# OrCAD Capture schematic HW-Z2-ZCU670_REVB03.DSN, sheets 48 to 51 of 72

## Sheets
48 048 PMIC 2 Power Stage: size Custom
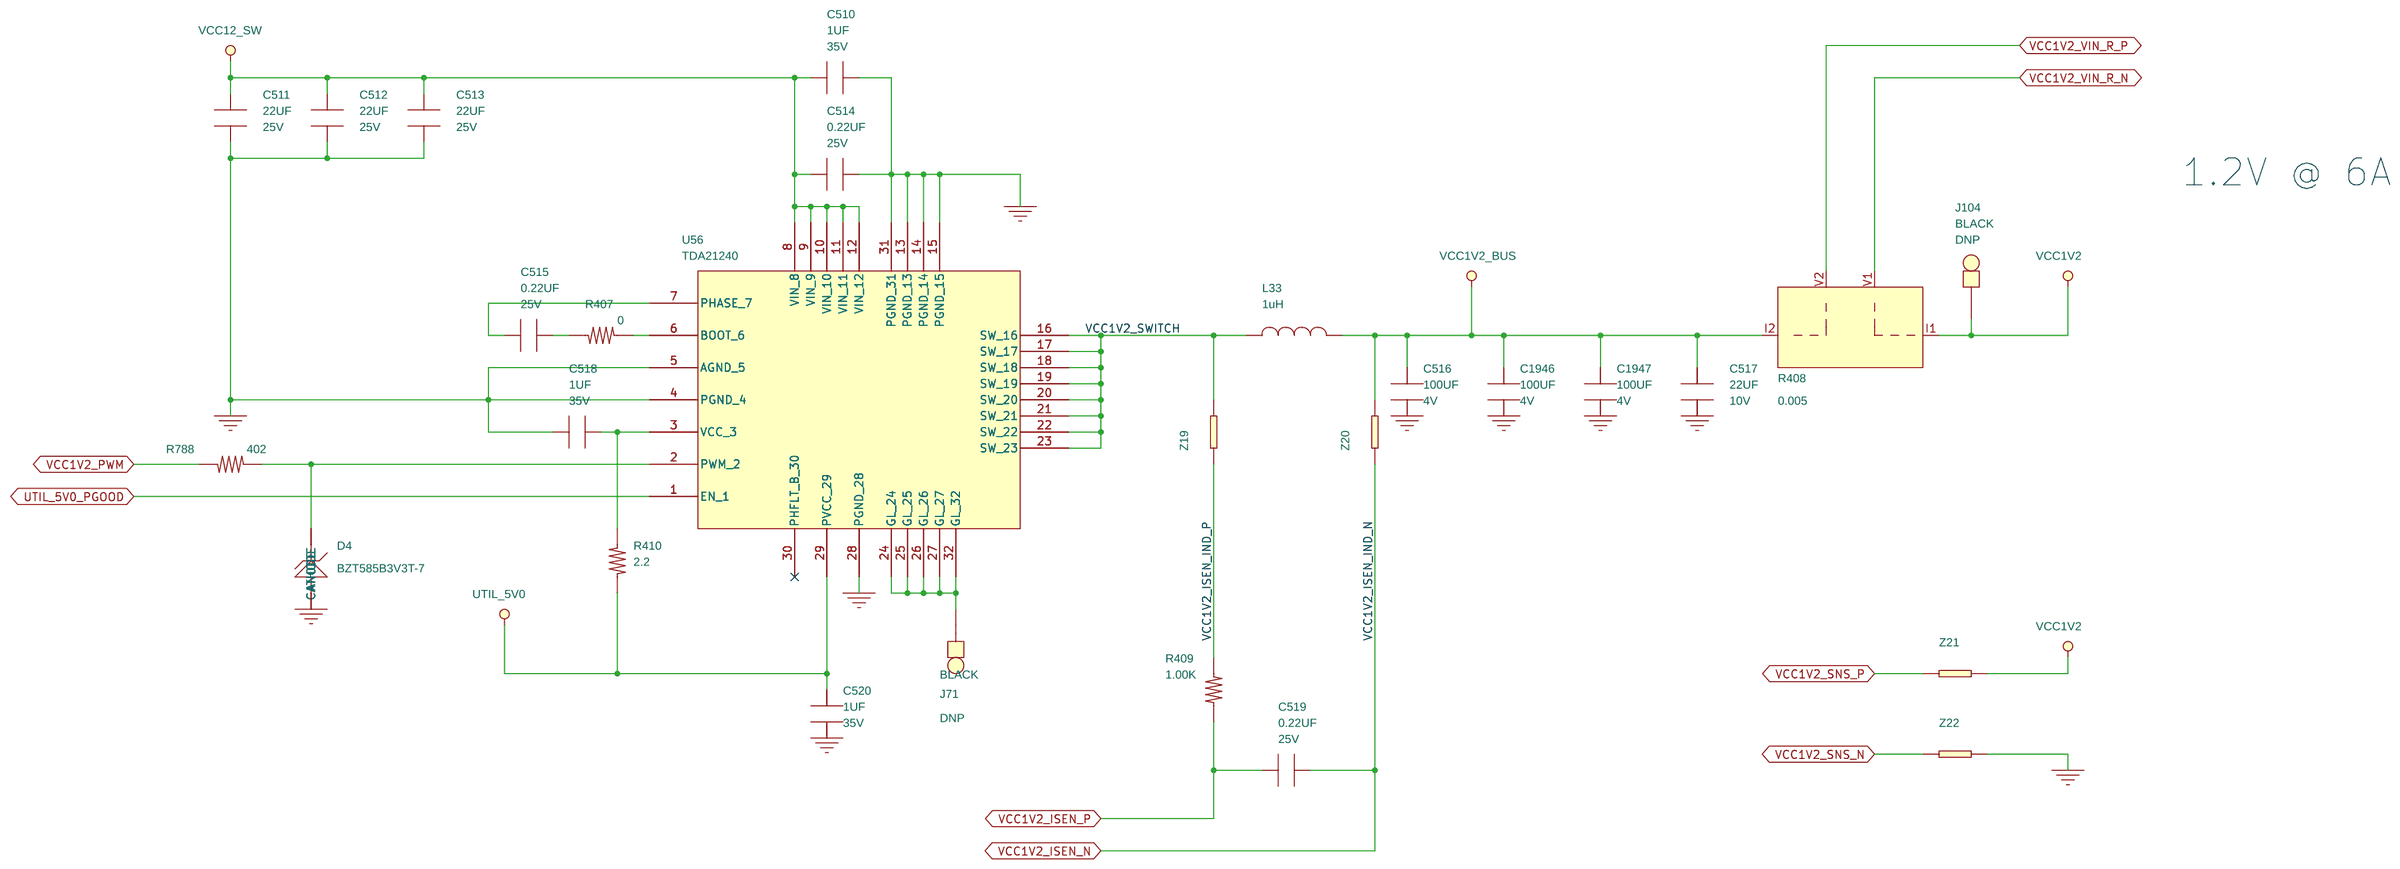
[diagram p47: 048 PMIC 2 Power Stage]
49 049 PMIC 3: size Custom
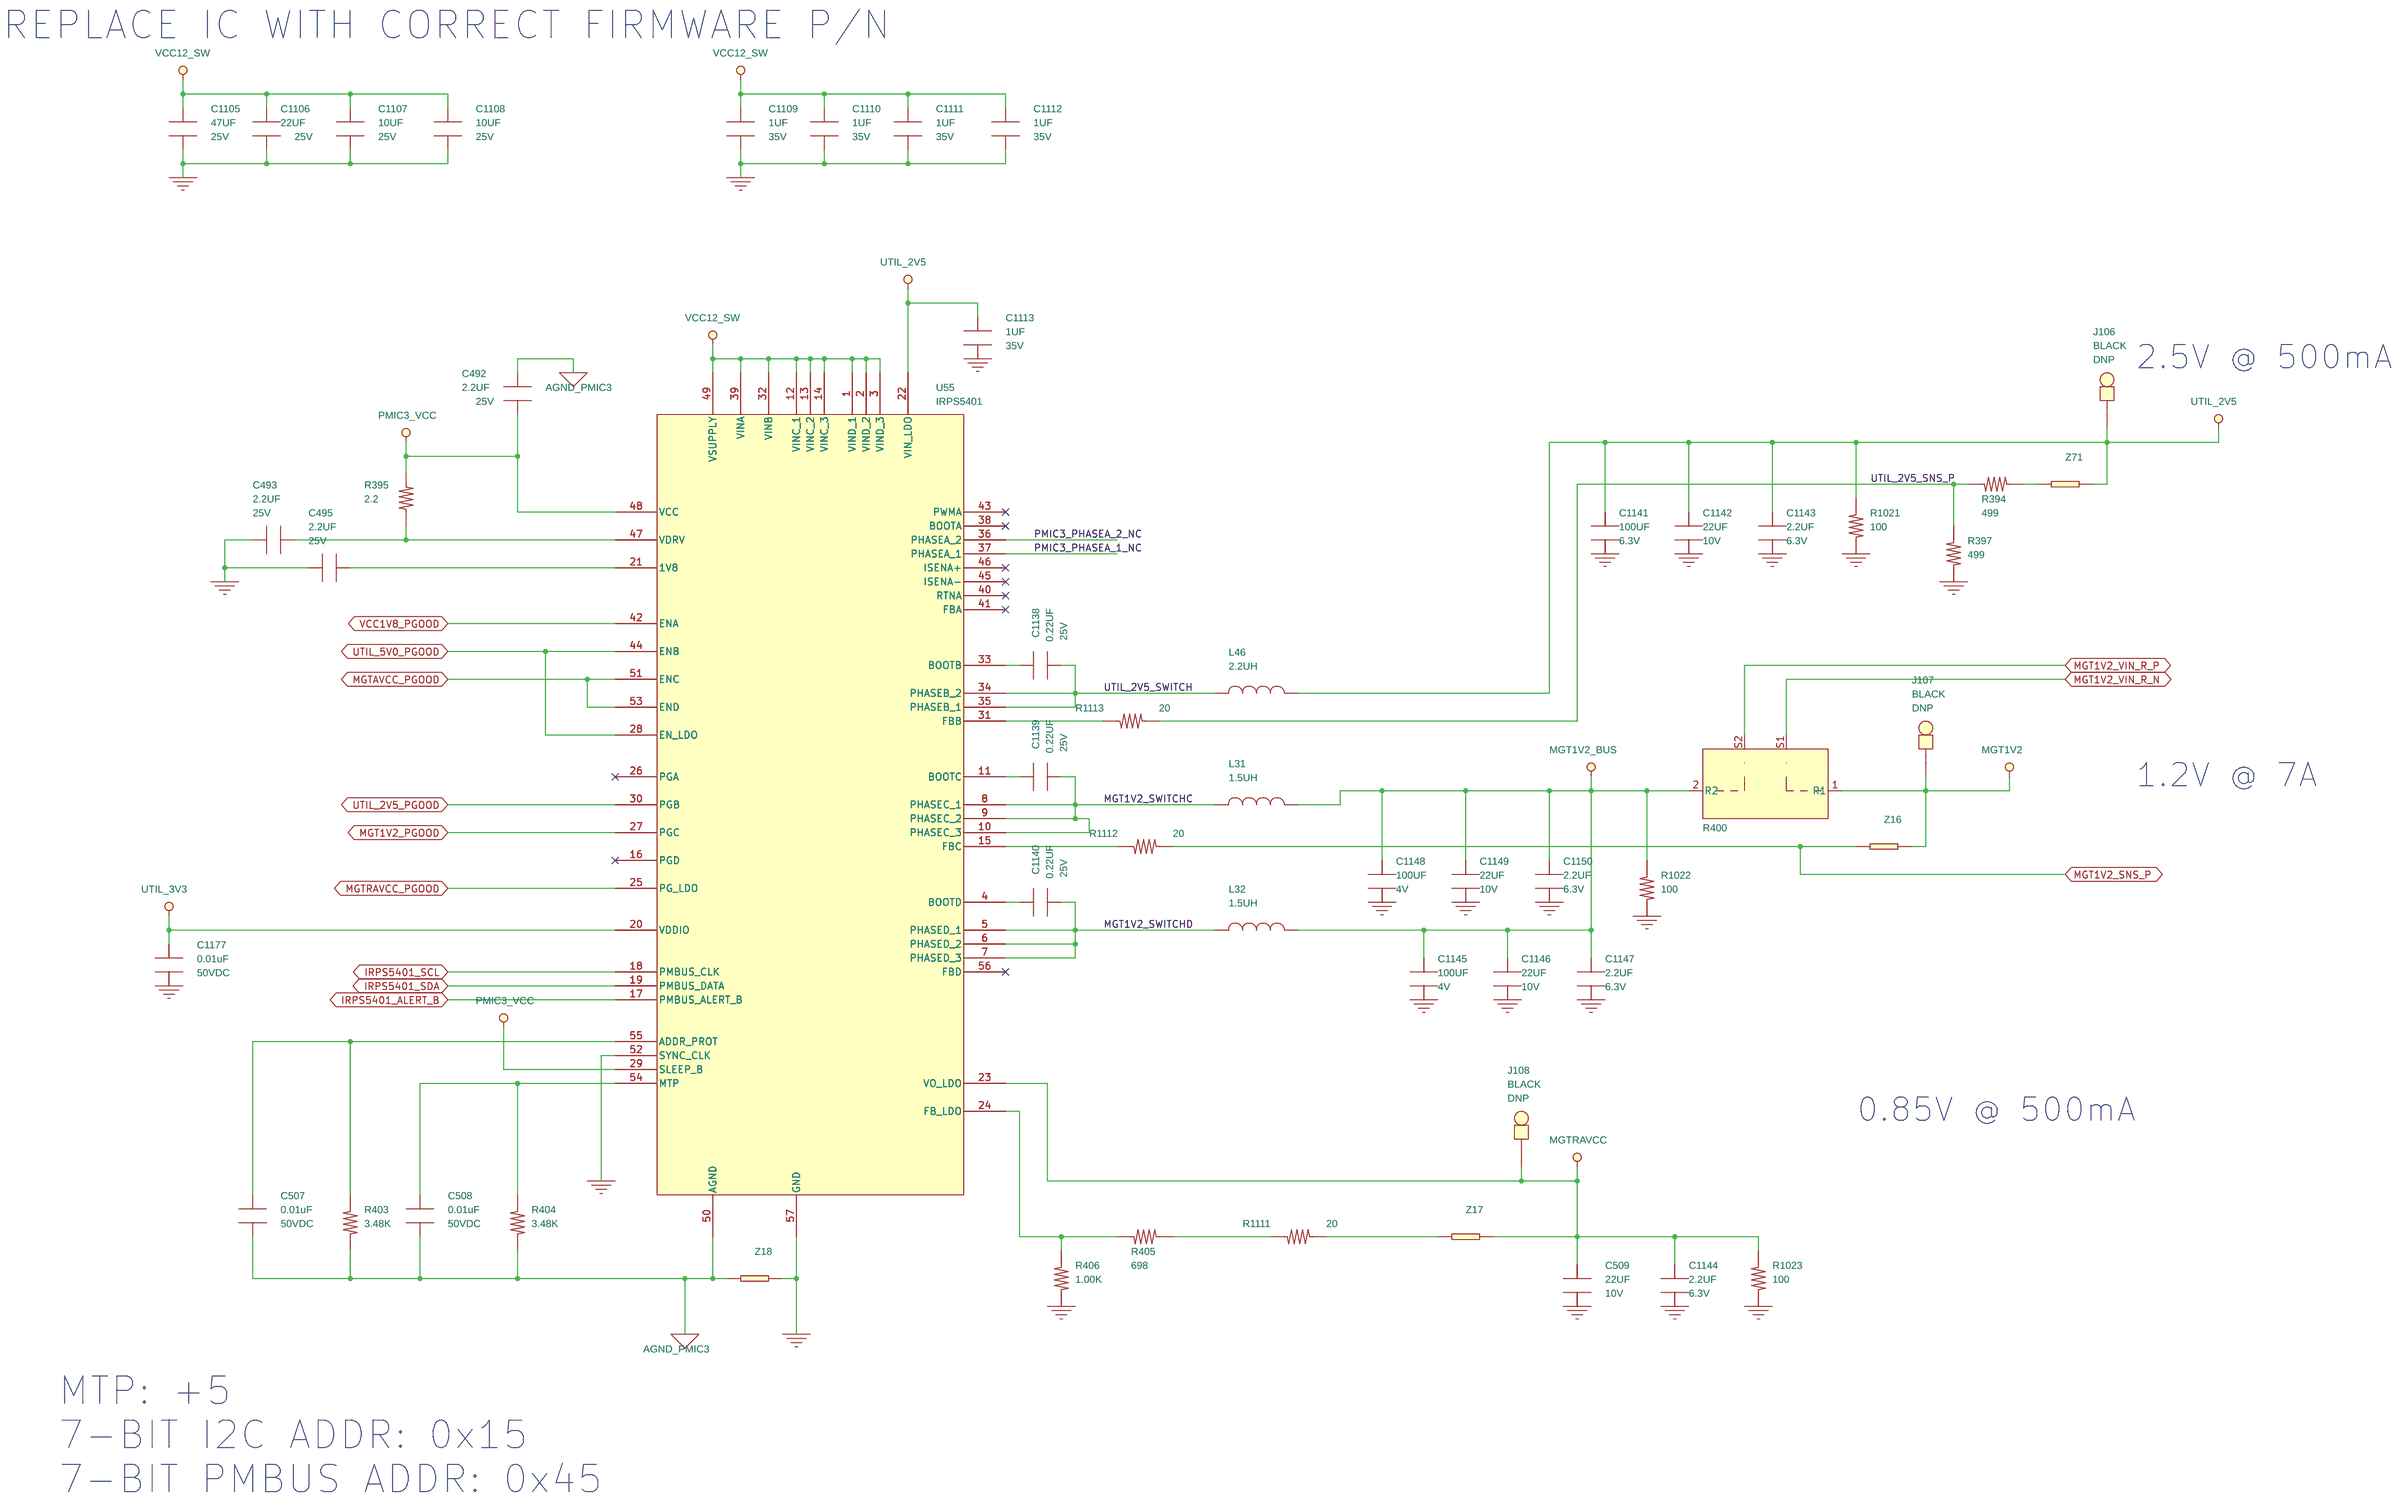
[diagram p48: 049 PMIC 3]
50 050 VCCINT_IO_BRAM_PS 18A Reg: size Custom
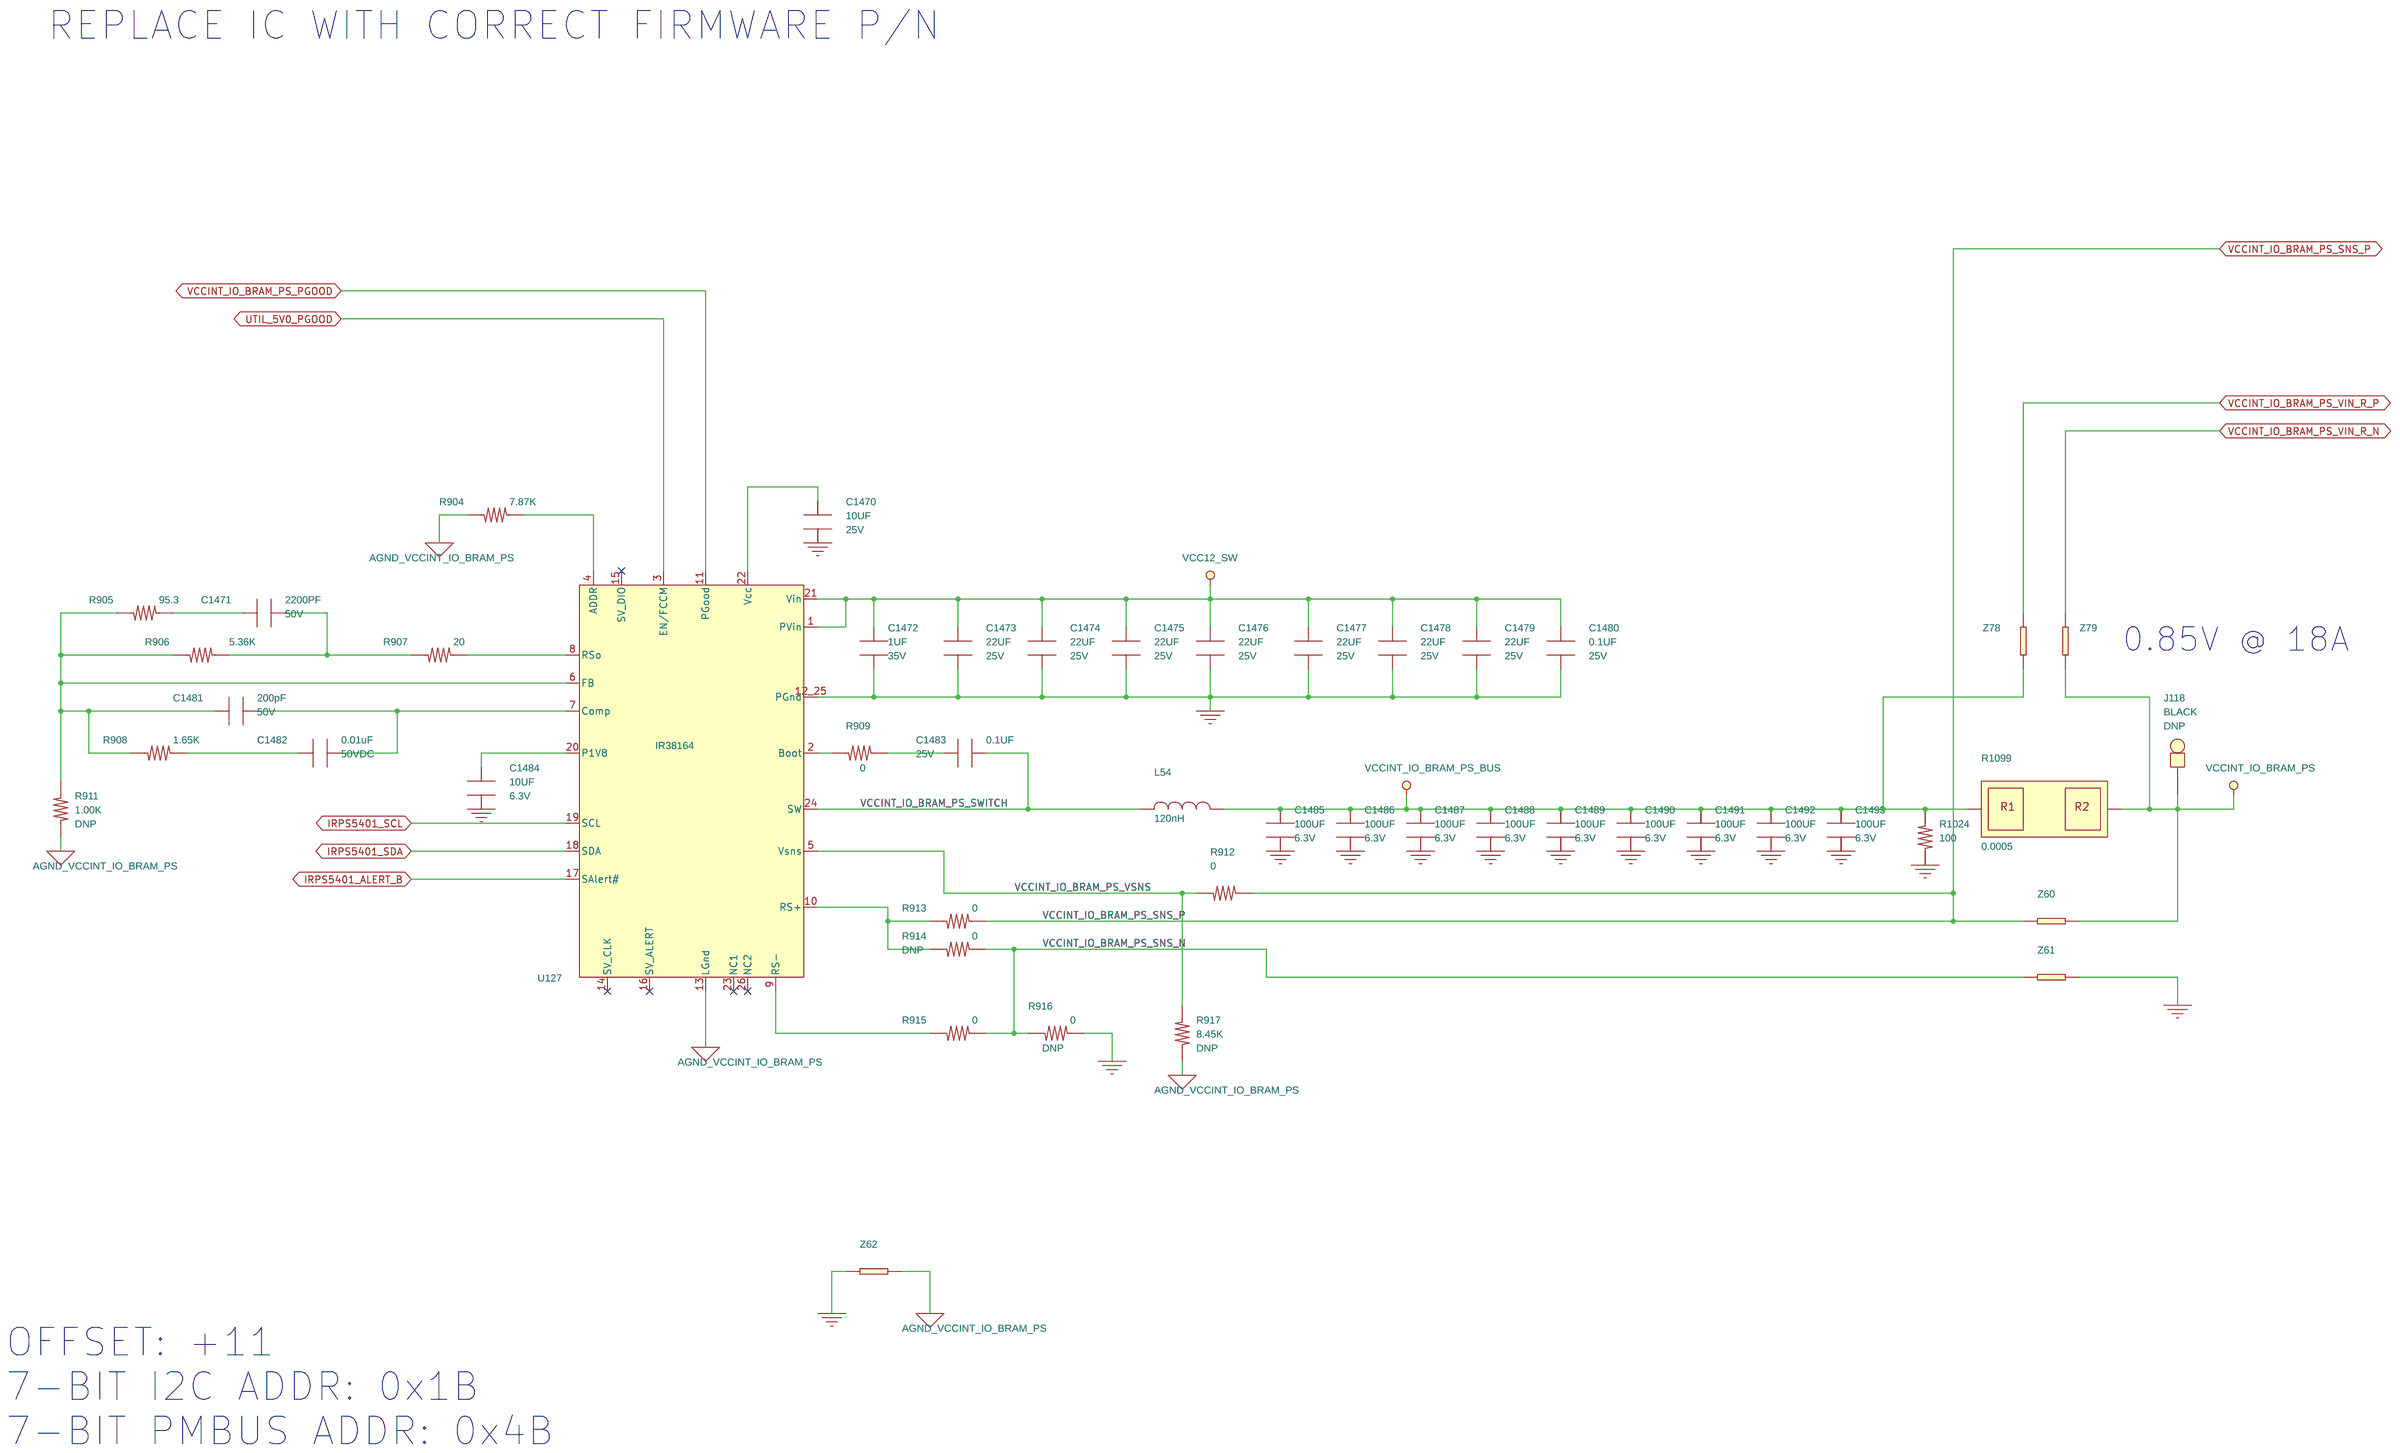
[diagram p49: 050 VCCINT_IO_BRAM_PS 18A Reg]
51 051 MGTAVCC 4A Regulator: size Custom
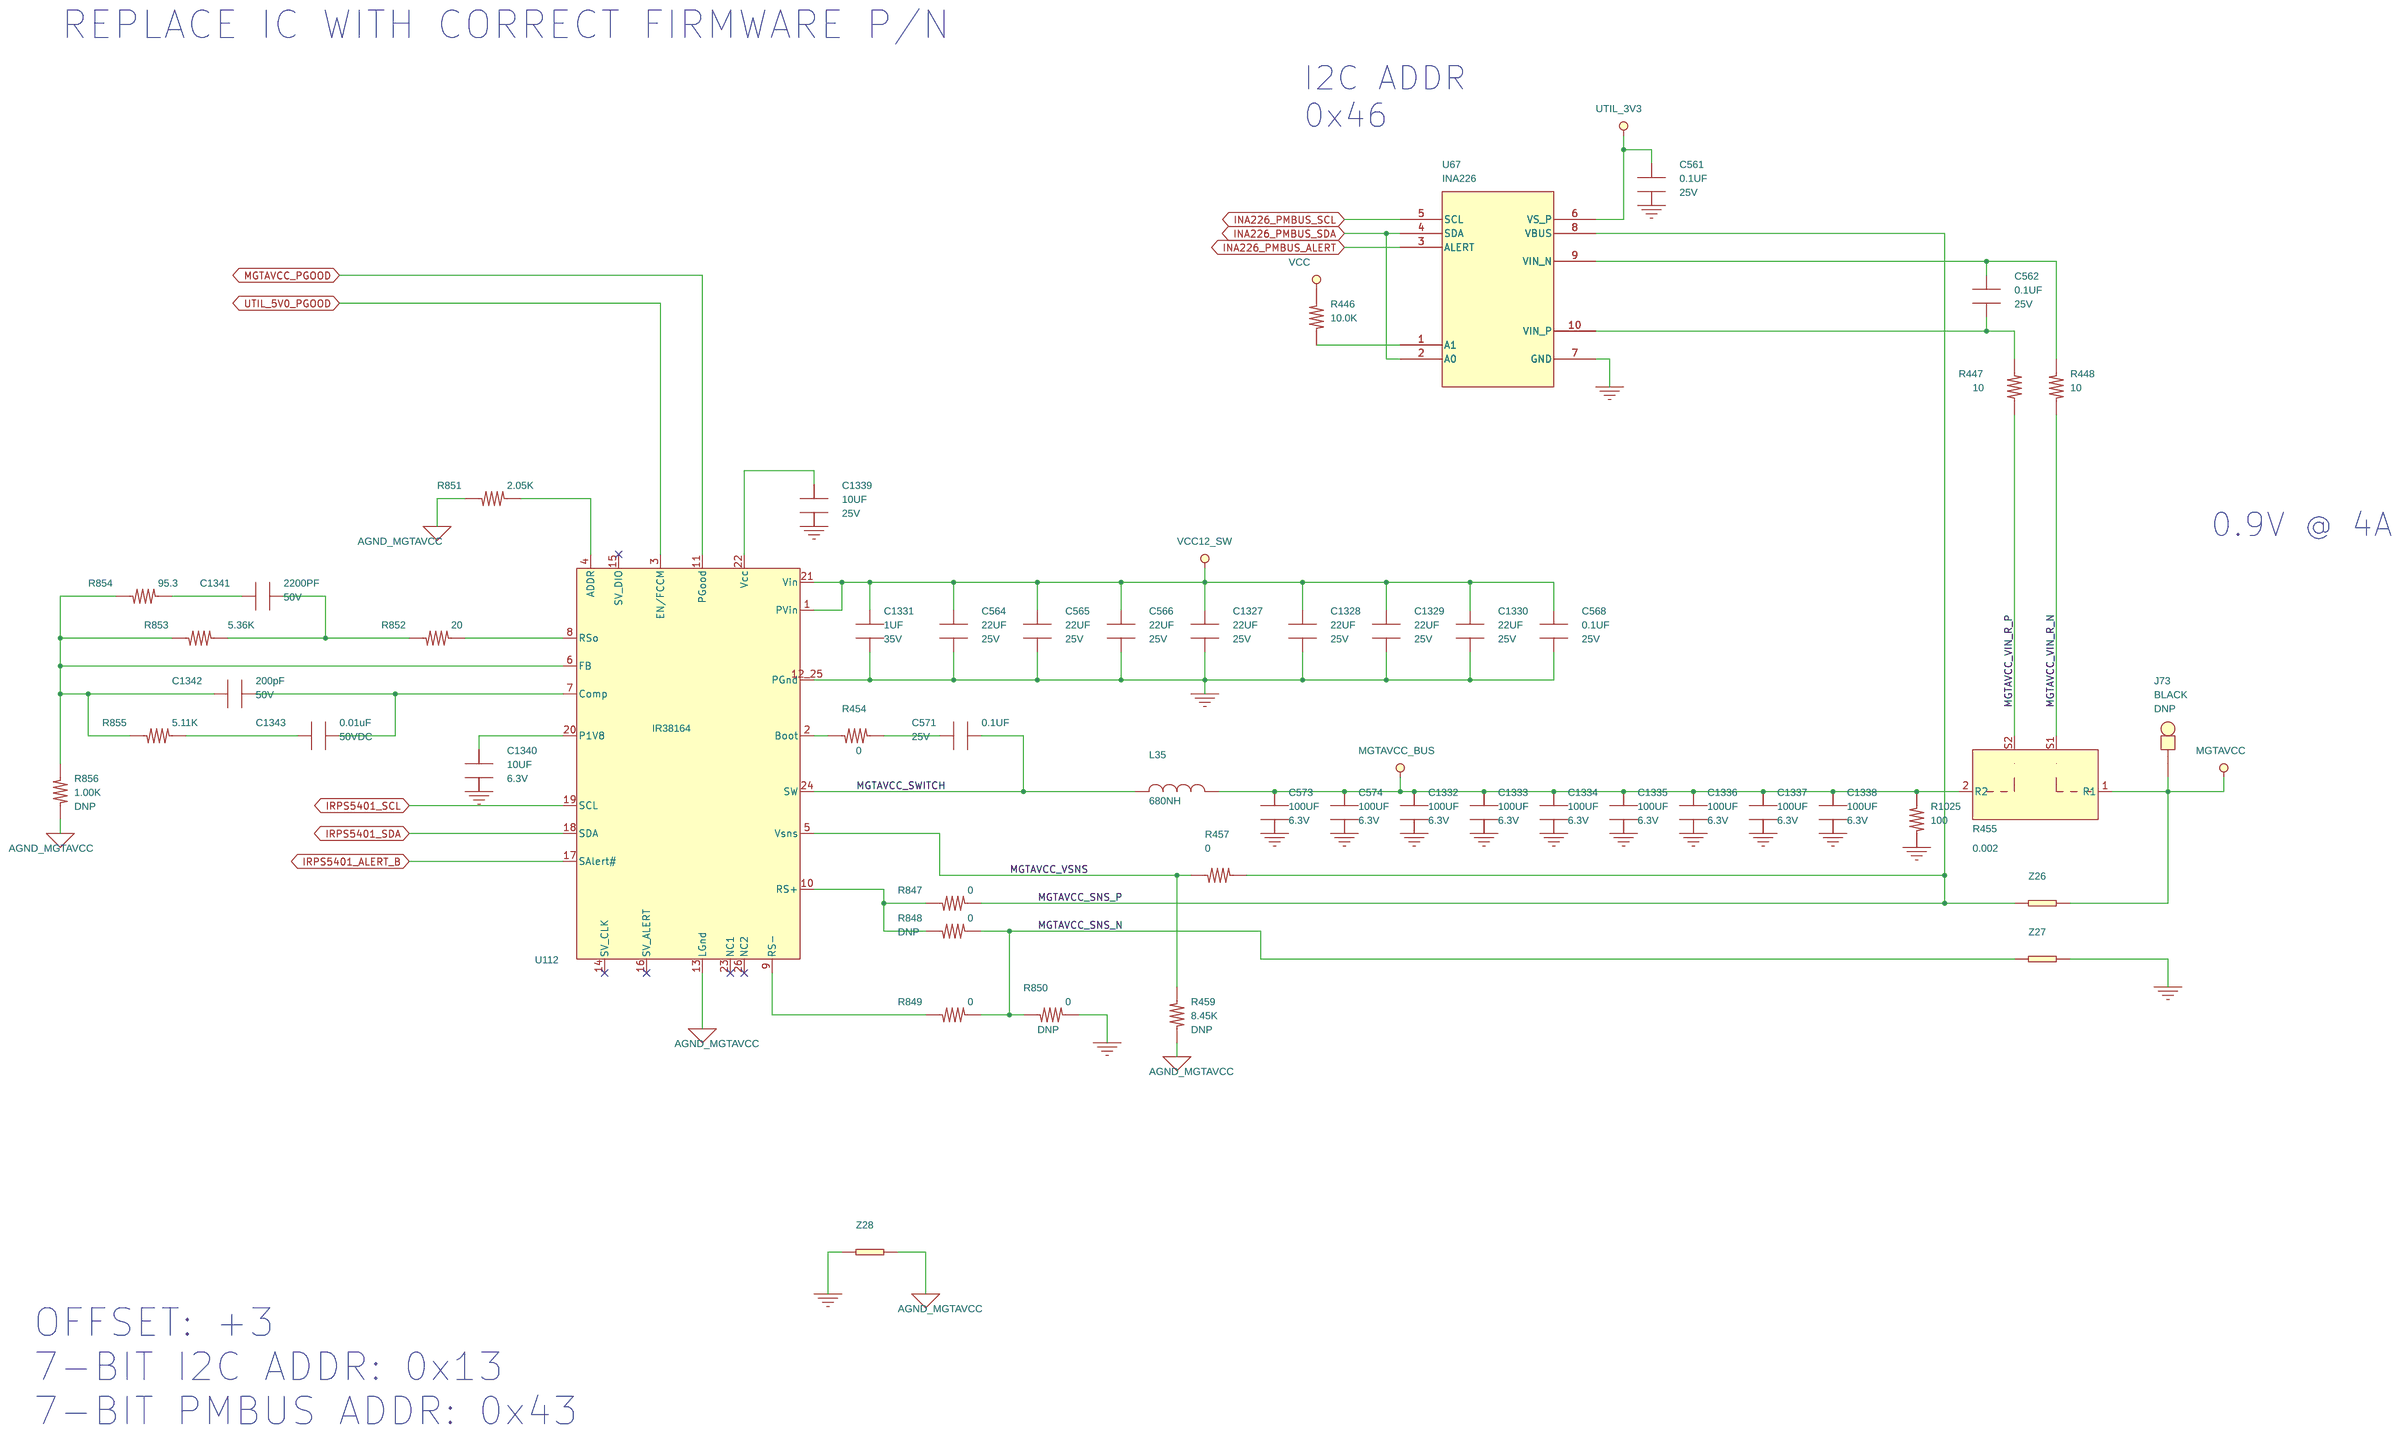
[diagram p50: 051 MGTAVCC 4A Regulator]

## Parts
sheet 048 PMIC 2 Power Stage
C510  1UF  [CAPC100X50X60]
C511  22UF  [CAPC320X160X180]
C512  22UF  [CAPC320X160X180]
C513  22UF  [CAPC320X160X180]
C514  0.22UF  [CAPC100X50X55]
C515  0.22UF  [CAPC100X50X55]
C516  100UF  [CAPC200X125X145]
C517  22UF  [CAPC200X125X145]
C518  1UF  [CAPC100X50X60]
C519  0.22UF  [CAPC100X50X55]
C520  1UF  [CAPC100X50X60]
C1946  100UF  [CAPC200X125X145]
C1947  100UF  [CAPC200X125X145]
D4  BZT585B3V3T-7  [SOD_523]
J71  BLACK  [TP_KEY_MINI]
J104  BLACK  [TP_KEY_MINI]
L33  1uH  [IND_WURTH_74439344010]
R407  0  [RESC100X50X40]
R408  0.005  [1224_SMT]
R409  1.00K  [RESC100X50X40]
R410  2.2  [RESC160X80X55]
R788  402  [RESC100X50X40]
U56  TDA21240  [TDA21240]
Z19  0201_SHORT  [0201_SHORT]
Z20  0201_SHORT  [0201_SHORT]
Z21  0201_SHORT  [0201_SHORT]
Z22  0201_SHORT  [0201_SHORT]
sheet 049 PMIC 3
C492  2.2UF  [CAPC200X125X135]
C493  2.2UF  [CAPC200X125X135]
C495  2.2UF  [CAPC200X125X135]
C507  0.01uF  [CAPC100X50X55]
C508  0.01uF  [CAPC100X50X55]
C509  22UF  [CAPC200X125X145]
C1105  47UF  [CAPC320X160X180]
C1106  22UF  [CAPC320X160X180]
C1107  10UF  [CAPC320X250X220]
C1108  10UF  [CAPC320X250X220]
C1109  1UF  [CAPC100X50X60]
C1110  1UF  [CAPC100X50X60]
C1111  1UF  [CAPC100X50X60]
C1112  1UF  [CAPC100X50X60]
C1113  1UF  [CAPC100X50X60]
C1138  0.22UF  [CAPC100X50X55]
C1139  0.22UF  [CAPC100X50X55]
C1140  0.22UF  [CAPC100X50X55]
C1141  100UF  [CAPC320X160X180]
C1142  22UF  [CAPC200X125X145]
C1143  2.2UF  [CAPC100X50X55]
C1144  2.2UF  [CAPC100X50X55]
C1145  100UF  [CAPC200X125X145]
C1146  22UF  [CAPC200X125X145]
C1147  2.2UF  [CAPC100X50X55]
C1148  100UF  [CAPC200X125X145]
C1149  22UF  [CAPC200X125X145]
C1150  2.2UF  [CAPC100X50X55]
C1177  0.01uF  [CAPC100X50X55]
J106  BLACK  [TP_KEY_MINI]
J107  BLACK  [TP_KEY_MINI]
J108  BLACK  [TP_KEY_MINI]
L31  1.5UH  [IND_SRP4020TA]
L32  1.5UH  [IND_SRP4020TA]
L46  2.2UH  [IND_SRP4020TA]
R394  499  [RESC100X50X40]
R395  2.2  [RESC160X80X55]
R397  499  [RESC100X50X40]
R400  0.002  [RES_WSL3637]
R403  3.48K  [RESC100X50X40]
R404  3.48K  [RESC100X50X40]
R405  698  [RESC100X50X40]
R406  1.00K  [RESC100X50X40]
R1021  100  [RESC100X50X40]
R1022  100  [RESC100X50X40]
R1023  100  [RESC100X50X40]
R1111  20  [RESC100X50X40]
R1112  20  [RESC100X50X40]
R1113  20  [RESC100X50X40]
U55  IRPS5401  [irps5401mtrpbf]
Z16  0201_SHORT  [0201_SHORT]
Z17  0201_SHORT  [0201_SHORT]
Z18  0201_SHORT  [0201_SHORT]
Z71  0201_SHORT  [0201_SHORT]
sheet 050 VCCINT_IO_BRAM_PS 18A Reg
C1470  10UF  [CAPC320X250X220]
C1471  2200PF  [CAPC100X50X55]
C1472  1UF  [CAPC100X50X60]
C1473  22UF  [CAPC320X160X180]
C1474  22UF  [CAPC320X160X180]
C1475  22UF  [CAPC320X160X180]
C1476  22UF  [CAPC320X160X180]
C1477  22UF  [CAPC320X160X180]
C1478  22UF  [CAPC320X160X180]
C1479  22UF  [CAPC320X160X180]
C1480  0.1UF  [CAPC100X50X55]
C1481  200pF  [CAPC100X50X55]
C1482  0.01uF  [CAPC100X50X55]
C1483  0.1UF  [CAPC100X50X55]
C1484  10UF  [CAPC100X50X70]
C1485  100UF  [CAPC320X160X180]
C1486  100UF  [CAPC320X160X180]
C1487  100UF  [CAPC320X160X180]
C1488  100UF  [CAPC320X160X180]
C1489  100UF  [CAPC320X160X180]
C1490  100UF  [CAPC320X160X180]
C1491  100UF  [CAPC320X160X180]
C1492  100UF  [CAPC320X160X180]
C1493  100UF  [CAPC320X160X180]
J118  BLACK  [TP_KEY_MINI]
L54  120nH  [IND_KEMET_MPCH0730]
R904  7.87K  [RESC100X50X40]
R905  95.3  [RESC100X50X40]
R906  5.36K  [RESC100X50X40]
R907  20  [RESC100X50X40]
R908  1.65K  [RESC100X50X40]
R909  0  [RESC100X50X40]
R911  1.00K  [RESC100X50X40]
R912  0  [RESC100X50X40]
R913  0  [RESC100X50X40]
R914  0  [RESC100X50X40]
R915  0  [RESC100X50X40]
R916  0  [RESC100X50X40]
R917  8.45K  [RESC100X50X40]
R1024  100  [RESC100X50X40]
R1099  0.0005  [RES_CSS2775]
U127  IR38164  [QFN_IR38164_26]
Z60  0201_SHORT  [0201_SHORT]
Z61  0201_SHORT  [0201_SHORT]
Z62  0201_SHORT  [0201_SHORT]
Z78  0201_SHORT  [0201_SHORT]
Z79  0201_SHORT  [0201_SHORT]
sheet 051 MGTAVCC 4A Regulator
C561  0.1UF  [CAPC100X50X55]
C562  0.1UF  [CAPC100X50X55]
C564  22UF  [CAPC320X160X180]
C565  22UF  [CAPC320X160X180]
C566  22UF  [CAPC320X160X180]
C568  0.1UF  [CAPC100X50X55]
C571  0.1UF  [CAPC100X50X55]
C573  100UF  [CAPC320X160X180]
C574  100UF  [CAPC320X160X180]
C1327  22UF  [CAPC320X160X180]
C1328  22UF  [CAPC320X160X180]
C1329  22UF  [CAPC320X160X180]
C1330  22UF  [CAPC320X160X180]
C1331  1UF  [CAPC100X50X60]
C1332  100UF  [CAPC320X160X180]
C1333  100UF  [CAPC320X160X180]
C1334  100UF  [CAPC320X160X180]
C1335  100UF  [CAPC320X160X180]
C1336  100UF  [CAPC320X160X180]
C1337  100UF  [CAPC320X160X180]
C1338  100UF  [CAPC320X160X180]
C1339  10UF  [CAPC320X250X220]
C1340  10UF  [CAPC100X50X70]
C1341  2200PF  [CAPC100X50X55]
C1342  200pF  [CAPC100X50X55]
C1343  0.01uF  [CAPC100X50X55]
J73  BLACK  [TP_KEY_MINI]
L35  680NH  [IND_SRP7050TA]
R446  10.0K  [RESC100X50X40]
R447  10  [RESC100X50X40]
R448  10  [RESC100X50X40]
R454  0  [RESC100X50X40]
R455  0.002  [RES_WSL3637]
R457  0  [RESC100X50X40]
R459  8.45K  [RESC100X50X40]
R847  0  [RESC100X50X40]
R848  0  [RESC100X50X40]
R849  0  [RESC100X50X40]
R850  0  [RESC100X50X40]
R851  2.05K  [RESC100X50X40]
R852  20  [RESC100X50X40]
R853  5.36K  [RESC100X50X40]
R854  95.3  [RESC100X50X40]
R855  5.11K  [RESC100X50X40]
R856  1.00K  [RESC100X50X40]
R1025  100  [RESC100X50X40]
U67  INA226  [DGS_MSOP_10]
U112  IR38164  [QFN_IR38164_26]
Z26  0201_SHORT  [0201_SHORT]
Z27  0201_SHORT  [0201_SHORT]
Z28  0201_SHORT  [0201_SHORT]

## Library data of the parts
C510 C518 C520 C1109-C1113 C1331 C1472 = CAP_NP: Cap Cer 1uF 10% 35V X5R 0402; ALT_SYMBOLS: CAPC100X50X60RND; Agile Part Number: CAP-00165-01; CIP Link: http://xsjbrdwin1/CIP-E/Component/Index/All?pn=100192; Dielectric Type: X5R; OWNER: 3709; PRICE: 0.04; Part Type: CERAMIC; PartType: CERAMIC; ROHS: Yes; Tolerance: 10%; Voltage: 35V; barcode: 100192
C511-C513 C564-C566 C1106 C1327-C1330 C1473-C1479 = CAP_NP: Cap Cer 22uF 10% 25V X5R 1206; ALT_SYMBOLS: CAPC320X160X180RND; Agile Part Number: CAP-00058-01; CIP Link: http://xsjbrdwin1/CIP-E/Component/Index/All?pn=100026; Dielectric Type: X5R; OWNER: 3709; PRICE: 0.17; Part Type: CERAMIC; PartType: CERAMIC; ROHS: Yes; Tolerance: 10%; Voltage: 25V; barcode: 100026
C514 C515 C519 C1138-C1140 = CAP_NP: Cap Cer 220nF 10%  25V X6S 0402; ALT_SYMBOLS: (0402,C402-25,CAPC100X50X55L25NRND,CAPC100X50X55L30NRND,CAPC100X50X55L30N); Agile Part Number: CAP-00005-01; CIP Link: http://xsjbrdwin1/CIP-E/Component/Index/All?pn=100180; Dielectric Type: X6S; OWNER: 6176; PRICE: 0.03; Part Type: CERAMIC; PartType: CERAMIC; ROHS: Yes; Tolerance: 10%; Voltage: 25V; barcode: 100180
C516 C1946 C1947 = CAP_NP: Cap Cer 100uF 20% 4V X6S 0805; ALT_SYMBOLS: CAPC200X125X145RND; Agile Part Number: CAP-00038-01; CIP Link: http://xsjbrdwin1/CIP-E/Component/Index/All?pn=100257; Dielectric Type: X6S; OWNER: 3709; PRICE: 0.17; Part Type: CERAMIC; PartType: CERAMIC; ROHS: Yes; Tolerance: 20%; Voltage: 4V; barcode: 100257
C509 C517 C1142 C1146 C1149 = CAP_NP: Cap Cer 22uF 20% 10V X6S 0805; Agile Part Number: CAP-00021-01; CIP Link: http://xsjbrdwin1/CIP-E/Component/Index/All?pn=100280; Dielectric Type: X6S; OWNER: 3709; PRICE: 0.17; Part Type: CERAMIC; PartType: CERAMIC; ROHS: Yes; Tolerance: 20%; Voltage: 10V; barcode: 100280
D4 = DIODE_ZENER: DIODE ZENER 3.3V 350MW SOD523; Agile Part Number: DIO-00095-01; Barcode: 70000026; CIP Link: http://xsjbrdwin1/CIP-E/Component/Index/All?pn=70000026; Part Type: ZENER; Rated Power: 350mW; Voltage: 3.3V
J71 J73 J104 J106-J108 J118 = TP-HOOK: Conn Test Point Mini Loop Black TH; ALT_SYMBOLS: TP_KEY_MINI_DNP; ASSEMBLY_OPTIONS: DNP; Agile Part Number: CON-00272-01; Barcode: 900015; CIP Link: http://xsjbrdwin1/CIP-E/Component/Index/All?pn=900015; OWNER: 3709; Part Type: TEST POINT; PartType: TEST POINT; Pins: 1PIN; Pitch: 0.04IN; ROHS: Yes
L33 = IND: Ind 1uH 20% 12A Irms 27.5A Isat 6.05mR 6.65x6.45mm SMT Shielded; Agile Part Number: IND-00179-01; Barcode: 30000020; CIP Link: http://xsjbrdwin1/CIP-E/Component/Index/All?pn=30000020; OWNER: 3709; PRICE: 0.5; Part Type: Unassigned Part Type; PartType: POWER INDUCTOR; ROHS: YES; Tolerance: 20%
R407 R454 R909 = RES: Res 0R 50mR 1A 0402; ALT_SYMBOLS: RESC100X50X40RND; Agile Part Number: RES-00010-01; Barcode: 200012; CIP Link: http://xsjbrdwin1/CIP-E/Component/Index/All?pn=200012; OWNER: 4001; PRICE: 0.01; Part Type: SMT - 5%; PartType: SMT - 5%; Power: 1/10W; ROHS: Yes; Tolerance: 5%; primarykey: 13
R408 = RES_OHMITE_LVK25: Res 5mR 1% 2W 100PPM 1224 Wide 4-Term; Agile Part Number: RES-00118-01; Barcode: 200097; CIP Link: http://xsjbrdwin1/CIP-E/Component/Index/All?pn=200097; OWNER: 3709; PRICE: 0.89; Part Type: SMT -CURSNS; PartType: SMT -CURSNS; Power: 2W; ROHS: Yes; Rated Power: 2W; Tolerance: 1%; primarykey: 29
R409 = RES: Res 1K 1% 1/16W 100PPM 50V 0402; ALT_SYMBOLS: RESC100X50X40RND; Agile Part Number: RES-00027-01; Barcode: 200098; CIP Link: http://xsjbrdwin1/CIP-E/Component/Index/All?pn=200098; OWNER: 3709; PRICE: 0; Part Type: SMT - 1%; PartType: SMT - 1%; Power: 1/10W; ROHS: Yes; Rated Power: 1/16W; Tolerance: 1%; primarykey: 446
R395 R410 = RES: Res 2R2 1% 1/10W 200PPM 0603; ALT_SYMBOLS: RESC160X80X55RND; Agile Part Number: RES-00241-01; Barcode: 200258; CIP Link: http://xsjbrdwin1/CIP-E/Component/Index/All?pn=200258; OWNER: 3501; PRICE: 0.01; Part Type: SMT - 1%; PartType: SMT - 1%; Power: 1/10W; ROHS: Yes; Rated Power: 1/10W; Tolerance: 1%; primarykey: 293
R788 = RES: Res 402R 1% 1/16W 100PPM 50V 0402; ALT_SYMBOLS: (0402,C402-25,RESC100X50X40L25NRND); Agile Part Number: RES-00152-01; Barcode: 200142; CIP Link: http://xsjbrdwin1/CIP-E/Component/Index/All?pn=200142; Part Type: SMT - 1%; Rated Power: 1/16W; Tolerance: 1%
U56 = TDA21240: IC V. Reg Step-Down DC/DC Synch 16V 40A 1MHz PG-IQFN-30-2; Agile Part Number: ICS-00361-01; Barcode: 500556; CIP Link: http://xsjbrdwin1/CIP-E/Component/Index/All?pn=500556; Family: POWER MANAGEMENT; Part Type: POWER MANAGEMENT; ROHS: YES
Z16-Z22 Z26-Z28 Z60-Z62 Z71 Z78 Z79 = 0201_SHORT: PCB only 0201_SHORT; ASSEMBLY_OPTIONS: DNP; Barcode: 96000001; CIP Link: http://xsjbrdwin1/CIP-E/Component/Index/All?pn=96000001; OWNER: 3670; Part Type: PCB LAYOUT; PartType: PCB LAYOUT; ROHS: 0
C492 C493 C495 = CAP_NP: Cap Cer 2.2uF 10% 25V X7R 0805; ALT_SYMBOLS: CAPC200X125X135RND; Agile Part Number: CAP-00114-01; CIP Link: http://xsjbrdwin1/CIP-E/Component/Index/All?pn=100124; Dielectric Type: X7R; OWNER: 3709; PRICE: 0.03; Part Type: CERAMIC; PartType: CERAMIC; ROHS: Yes; Tolerance: 10%; Voltage: 25V; barcode: 100124
C507 C508 C1177 C1343 C1482 = CAP_NP: Cap Cer 10nF 10% 50V X7R 0402; ALT_SYMBOLS: CAPC100X50X55RND; Agile Part Number: CAP-00031-01; CIP Link: http://xsjbrdwin1/CIP-E/Component/Index/All?pn=100003; Dielectric Type: X7R; OWNER: 4001; PRICE: 0; Part Type: CERAMIC; PartType: CERAMIC; ROHS: Yes; Tolerance: 10%; Voltage: 50VDC; barcode: 100003
C1105 = CAP_NP: Cap Cer 47uF 20% 25V X5R 1206; ALT_SYMBOLS: CAPC320X160X180RND; Agile Part Number: CAP-00092-01; CIP Link: http://xsjbrdwin1/CIP-E/Component/Index/All?pn=100087; Dielectric Type: X5R; OWNER: 3709; PRICE: 0.18; Part Type: CERAMIC; PartType: CERAMIC; ROHS: Yes; Tolerance: 20%; Voltage: 25V; barcode: 100087
C1107 C1108 C1339 C1470 = CAP_NP: Cap Cer 10uF 10% 25V X5R 1210; ALT_SYMBOLS: CAPC320X250X220RND; Agile Part Number: CAP-00113-01; CIP Link: http://xsjbrdwin1/CIP-E/Component/Index/All?pn=100123; Dielectric Type: X5R; OWNER: 3709; PRICE: 0.18; Part Type: CERAMIC; PartType: CERAMIC; ROHS: Yes; Tolerance: 10%; Voltage: 25V; barcode: 100123
C1141 = CAP_NP: Cap Cer 100uF 20% 6.3V X5R 1206; ALT_SYMBOLS: 1206; Agile Part Number: CAP-00061-01; CIP Link: http://xsjbrdwin1/CIP-E/Component/Index/All?pn=100029; Dielectric Type: X5R; OWNER: 3709; PRICE: 0.35; Part Type: CERAMIC; PartType: CERAMIC; ROHS: Yes; Tolerance: 20%; Voltage: 6.3V; barcode: 100029
C1143 C1144 C1147 C1150 = CAP_NP: Cap Cer 2.2uF 20% 6.3V X5R 0402; Agile Part Number: CAP-00081-01; CIP Link: http://xsjbrdwin1/CIP-E/Component/Index/All?pn=100062; Dielectric Type: X5R; OWNER: 6176; PRICE: 0.06; Part Type: CERAMIC; PartType: CERAMIC; ROHS: Yes; Tolerance: 20%; Voltage: 6.3V; barcode: 100062
C1145 C1148 = CAP_NP: Cap Cer 100uF 20% 4V X6S 0805; ALT_SYMBOLS: CAPC200X125X145RND; Agile Part Number: CAP-00038-01; CIP Link: http://xsjbrdwin1/CIP-E/Component/Index/All?pn=100257; Dielectric Type: X6S; OWNER: 3709; PRICE: 0.35; Part Type: CERAMIC; PartType: CERAMIC; ROHS: Yes; Tolerance: 20%; Voltage: 4V; barcode: 100257
L31 L32 = IND: Ind 1.5uH 20% 4.5A Irms 7A Isat 42mR 4.45x4.06mm SMT Shielded; Agile Part Number: IND-00091-01; Barcode: 300176; CIP Link: http://xsjbrdwin1/CIP-E/Component/Index/All?pn=300176; OWNER: 3709; PRICE: 0.5; Part Type: POWER INDUCTOR; PartType: POWER INDUCTOR; ROHS: YES; Tolerance: 20%
L46 = IND: Ind 2.2uH 20% 4A Irms 6A Isat 61mR 4.45x4.06mm SMT Shielded; Agile Part Number: IND-00090-01; Barcode: 300175; CIP Link: http://xsjbrdwin1/CIP-E/Component/Index/All?pn=300175; OWNER: 3709; PRICE: 0.5; Part Type: POWER INDUCTOR; PartType: POWER INDUCTOR; ROHS: YES; Tolerance: 20%
R394 R397 = RES: Res 499R 1% 1/16W 100PPM 50V 0402; ALT_SYMBOLS: RESC100X50X40RND; Agile Part Number: RES-00028-01; Barcode: 200071; CIP Link: http://xsjbrdwin1/CIP-E/Component/Index/All?pn=200071; OWNER: 10460; PRICE: 0; Part Type: SMT - 1%; PartType: SMT - 1%; Power: 1/10W; ROHS: Yes; Rated Power: 1/16W; Tolerance: 1%; primarykey: 79
R400 = RES_VISHAY_WSL: Res 2mR 1% 3W 75PPM 3637 4-Term; Agile Part Number: RES-00225-01; Barcode: 200240; CIP Link: http://xsjbrdwin1/CIP-E/Component/Index/All?pn=200240; Part Type: SMT -CURSNS; Rated Power: 3W; Tolerance: 1%
R403 = RES: Res 3K48 1% 1/16W 100PPM 50V 0402; ALT_SYMBOLS: RESC100X50X40RND; Agile Part Number: RES-00094-01; Barcode: 200058; CIP Link: http://xsjbrdwin1/CIP-E/Component/Index/All?pn=200058; OWNER: 3709; PRICE: 0; Part Type: SMT - 1%; PartType: SMT - 1%; Power: 1/10W; ROHS: Yes; Rated Power: 1/16W; Tolerance: 1%; primarykey: 34
R404 = RES: Res 3K48 1% 1/16W 100PPM 50V 0402; ALT_SYMBOLS: RESC100X50X40RND; Agile Part Number: RES-00094-01; Barcode: 200058; CIP Link: http://xsjbrdwin1/CIP-E/Component/Index/All?pn=200058; OWNER: 3501; PRICE: 0; Part Type: SMT - 1%; PartType: SMT - 1%; Power: 1/10W; ROHS: Yes; Rated Power: 1/16W; Tolerance: 1%; primarykey: 153
R405 = RES: Res 698R 1% 1/16W 100PPM 50V 0402; Agile Part Number: RES-00109-01; Barcode: 200080; CIP Link: http://xsjbrdwin1/CIP-E/Component/Index/All?pn=200080; OWNER: 6176; PRICE: 0; Part Type: SMT - 1%; PartType: SMT - 1%; Power: 1/10W; ROHS: Yes; Rated Power: 1/16W; Tolerance: 1%; primarykey: 391
R406 = RES: Res 1K 1% 1/16W 100PPM 50V 0402; ALT_SYMBOLS: RESC100X50X40RND; Agile Part Number: RES-00027-01; Barcode: 200098; CIP Link: http://xsjbrdwin1/CIP-E/Component/Index/All?pn=200098; OWNER: 6176; PRICE: 0; Part Type: SMT - 1%; PartType: SMT - 1%; Power: 1/10W; ROHS: Yes; Rated Power: 1/16W; Tolerance: 1%; primarykey: 20
R1021-R1025 = RES: Res 100R 1% 1/16W 100PPM 50V 0402; ALT_SYMBOLS: RESC100X50X40RND; Agile Part Number: RES-00046-01; Barcode: 200024; CIP Link: http://xsjbrdwin1/CIP-E/Component/Index/All?pn=200024; Part Type: SMT - 1%; Rated Power: 1/16W; Tolerance: 1%
R1111-R1113 = RES: Res 20R 1% 1/16W 100PPM 50V 0402; ALT_SYMBOLS: RESC100X50X40RND; Agile Part Number: RES-00033-01; Barcode: 200119; CIP Link: http://xsjbrdwin1/CIP-E/Component/Index/All?pn=200119; OWNER: 4001; PRICE: 0; Part Type: SMT - 1%; PartType: SMT - 1%; Power: 1/16W; ROHS: Yes; Rated Power: 1/16W; Tolerance: 1%; primarykey: 78
U55 = IRPS5401: IC PMU 5-Ch Step-Down DC/DC 14V 2MHz I2C/PMBus QFN-56; Agile Part Number: ICS-00375-01; Barcode: 50000038; CIP Link: http://xsjbrdwin1/CIP-E/Component/Index/All?pn=50000038; Family: POWER MANAGEMENT; Part Type: POWER MANAGEMENT; ROHS: Yes
C1341 C1471 = CAP_NP: Cap Cer 2.2nF 10% 50V X7R 0402; ALT_SYMBOLS: CAPC100X50X55RND; Agile Part Number: CAP-00030-01; Barcode: 100095; CIP Link: http://xsjbrdwin1/CIP-E/Component/Index/All?pn=100095; Dielectric Type: X7R; Part Type: CERAMIC; Tolerance: 10%; Voltage: 50V
C561 C562 C568 C571 C1480 C1483 = CAP_NP: Cap Cer 100nF 10% 25V X5R 0402; ALT_SYMBOLS: CAPC100X50X55RND; Agile Part Number: CAP-00068-01; CIP Link: http://xsjbrdwin1/CIP-E/Component/Index/All?pn=100040; Dielectric Type: X5R; OWNER: 4001; PRICE: 0.01; Part Type: CERAMIC; PartType: CERAMIC; ROHS: Yes; Tolerance: 10%; Voltage: 25V; barcode: 100040
C1342 C1481 = CAP_NP: Cap Cer 200pF 5% 50V C0G 0402; Agile Part Number: CAP-00272-01; Barcode: 10000006; CIP Link: http://xsjbrdwin1/CIP-E/Component/Index/All?pn=10000006; Part Type: --\-\0402 (1005 Metric); Tolerance: 2%; Voltage: 50V
C1340 C1484 = CAP_NP: Cap Cer 10uF 20%  6.3V X6S 0402; ALT_SYMBOLS: CAPC100X50X55RND; Agile Part Number: CAP-00035-01; CIP Link: http://xsjbrdwin1/CIP-E/Component/Index/All?pn=100268; Dielectric Type: X6S; OWNER: 6176; PRICE: 0.06; Part Type: CERAMIC; PartType: CERAMIC; ROHS: Yes; Tolerance: 20%; Voltage: 6.3V; barcode: 100268
C573 C574 C1332-C1338 C1485-C1493 = CAP_NP: Cap Cer 100uF 20% 6.3V X5R 1206; ALT_SYMBOLS: 1206; Agile Part Number: CAP-00061-01; CIP Link: http://xsjbrdwin1/CIP-E/Component/Index/All?pn=100029; Dielectric Type: X5R; OWNER: 3709; PRICE: 0.17; Part Type: CERAMIC; PartType: CERAMIC; ROHS: Yes; Tolerance: 20%; Voltage: 6.3V; barcode: 100029
L54 = IND: Ind 120nH 20% 31A Irms 32A Isat 715uR 8.0x6.7mm SMT; Agile Part Number: IND-00176-01; Barcode: 30000014; CIP Link: http://xsjbrdwin1/CIP-E/Component/Index/All?pn=30000014; OWNER: 3709; PRICE: 0.5; Part Type: Inductors, Coils, Chokes\Surface Mount; PartType: POWER INDUCTOR; ROHS: YES; Tolerance: 20%
R904 = RES: Res 7K87 1% 1/16W 100PPM 50V 0402; Agile Part Number: RES-00216-01; Barcode: 200231; CIP Link: http://xsjbrdwin1/CIP-E/Component/Index/All?pn=200231; Part Type: SMT - 1%; Rated Power: 1/10W; Tolerance: 1%
R854 R905 = RES: Res 95R3 1% 1/16W 100PPM 50V 0402; Agile Part Number: RES-00472-01; Barcode: 200573; CIP Link: http://xsjbrdwin1/CIP-E/Component/Index/All?pn=200573; Part Type: SMT - 1%; Rated Power: 1/16W; Tolerance: 1%
R853 R906 = RES: Res 5K36 1% 1/16W 100PPM 50V 0402; ALT_SYMBOLS: RESC100X50X40RND; Agile Part Number: RES-00422-01; Barcode: 200489; CIP Link: http://xsjbrdwin1/CIP-E/Component/Index/All?pn=200489; Part Type: SMT - 1%; Rated Power: 1/16W; Tolerance: 1%
R852 R907 = RES: Res 20R 1% 1/16W 100PPM 50V 0402; ALT_SYMBOLS: RESC100X50X40RND; Agile Part Number: RES-00033-01; Barcode: 200119; CIP Link: http://xsjbrdwin1/CIP-E/Component/Index/All?pn=200119; Part Type: SMT - 1%; Rated Power: 1/16W; Tolerance: 1%
R908 = RES: RES SMD 1.65K OHM 1% 1/10W 0402; ALT_SYMBOLS: RESC100X50X40RND; Agile Part Number: RES-00284-01; Barcode: 200306; CIP Link: http://xsjbrdwin1/CIP-E/Component/Index/All?pn=200306; Part Type: SMT - 1%; Rated Power: 1/10W; Tolerance: 1%
R856 R911 = RES: Res 1K 1% 1/16W 100PPM 50V 0402; ALT_SYMBOLS: RESC100X50X40RND; ASSEMBLY_OPTIONS: DNP; Agile Part Number: RES-00027-01; Barcode: 200098; CIP Link: http://xsjbrdwin1/CIP-E/Component/Index/All?pn=200098; Part Type: SMT - 1%; Rated Power: 1/16W; Tolerance: 1%
R457 R847 R849 R912 R913 R915 = RES: Res 0R 50mR 1A 0402; ALT_SYMBOLS: RESC100X50X40RND; Agile Part Number: RES-00010-01; Barcode: 200012; CIP Link: http://xsjbrdwin1/CIP-E/Component/Index/All?pn=200012; OWNER: 3709; Part Type: SMT - 5%; PartType: SMT - 1%; Power: 1/10W; ROHS: Yes; Tolerance: 5%; primarykey: 144
R848 R850 R914 R916 = RES: Res 0R 50mR 1A 0402; ALT_SYMBOLS: RESC100X50X40RND; ASSEMBLY_OPTIONS: DNP; Agile Part Number: RES-00010-01; Barcode: 200012; CIP Link: http://xsjbrdwin1/CIP-E/Component/Index/All?pn=200012; OWNER: 3709; Part Type: SMT - 5%; PartType: SMT - 1%; Power: 1/10W; ROHS: Yes; Tolerance: 5%; primarykey: 144
R459 R917 = RES: RES SMD 8.45K OHM 1% 1/10W 0402; ASSEMBLY_OPTIONS: DNP; Agile Part Number: RES-00423-01; Barcode: 200490; CIP Link: http://xsjbrdwin1/CIP-E/Component/Index/All?pn=200490; OWNER: 3709; PRICE: 0; Part Type: SMT - 1%; PartType: SMT - 1%; Power: 1/10W; ROHS: Yes; Rated Power: 1/10W; Tolerance: 1%; primarykey: 442
R1099 = RES_CS_CHIP_RESISTOR: Res 500uR 1% 4W 50PPM 2725 Wide AEC-Q200; Agile Part Number: RES-00301-01; Barcode: 200332; CIP Link: http://xsjbrdwin1/CIP-E/Component/Index/All?pn=200332; Part Type: SMT -CURSNS; Rated Power: 4W; Tolerance: 1%
U112 U127 = IR38164: IC V. Reg Step-Down DC/DC Synch 16V 30A 1.5MHz PQFN-24; Agile Part Number: ICS-00507-01; Barcode: 50000035; CIP Link: http://xsjbrdwin1/CIP-E/Component/Index/All?pn=50000035; Part Type: Integrated Circuits (ICs)\--
L35 = IND: Ind 680nH 20% 18A Irms 24A Isat 4.5mR 7.3x6.7mm SMT Shielded; Agile Part Number: IND-00108-01; Barcode: 300211; CIP Link: http://xsjbrdwin1/CIP-E/Component/Index/All?pn=300211; OWNER: 3709; PRICE: 0.5; Part Type: POWER INDUCTOR; PartType: POWER INDUCTOR; ROHS: YES; Tolerance: 20%
R446 = RES: Res 10K 1% 1/16W 100PPM 50V 0402; ALT_SYMBOLS: RESC100X50X40RND; Agile Part Number: RES-00030-01; Barcode: 200025; CIP Link: http://xsjbrdwin1/CIP-E/Component/Index/All?pn=200025; OWNER: 4001; PRICE: 0; Part Type: SMT - 1%; PartType: SMT - 1%; Power: 1/10W; ROHS: Yes; Rated Power: 1/16W; Tolerance: 1%; primarykey: 1
R447 R448 = RES: Res 10R 1% 1/16W 100PPM 50V 0402; ALT_SYMBOLS: RESC100X50X40RND; Agile Part Number: RES-00025-01; Barcode: 200028; CIP Link: http://xsjbrdwin1/CIP-E/Component/Index/All?pn=200028; OWNER: 10460; PRICE: 0; Part Type: SMT - 1%; PartType: SMT - 1%; Power: 1/10W; ROHS: Yes; Rated Power: 1/16W; Tolerance: 1%; primarykey: 97
R455 = RES_VISHAY_WSL: Res 2mR 1% 3W 75PPM 3637 4-Term; Agile Part Number: RES-00225-01; Barcode: 200240; CIP Link: http://xsjbrdwin1/CIP-E/Component/Index/All?pn=200240; OWNER: 3709; PRICE: 0.84; Part Type: SMT -CURSNS; PartType: SMT -CURSNS; Power: 3W; ROHS: Yes; Rated Power: 3W; Tolerance: 1%; primarykey: 95
R851 = RES: Res 2K05 1% 1/16W 100PPM 50V 0402; Agile Part Number: RES-00079-01; Barcode: 200042; CIP Link: http://xsjbrdwin1/CIP-E/Component/Index/All?pn=200042; Part Type: SMT - 1%; Rated Power: 1/16W; Tolerance: 1%
R855 = RES: RES SMD 5.11K OHM 1% 1/10W 0402; Agile Part Number: RES-00249-01; Barcode: 200267; CIP Link: http://xsjbrdwin1/CIP-E/Component/Index/All?pn=200267; Part Type: SMT - 1%; Rated Power: 1/10W; Tolerance: 1%
U67 = INA226: IC Power Mon I2C 36Vin 5V VSSOP-10; Agile Part Number: ICS-00186-01; Barcode: 500247; CIP Link: http://xsjbrdwin1/CIP-E/Component/Index/All?pn=500247; Family: OPAMP; Part Type: OPAMP; ROHS: Yes

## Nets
AGND_MGTAVCC: R459.2 R851.1 R856.2 U112.13(LGnd) Z28.1(NET1)
AGND_PMIC3: C492.1 C507.2 C508.2 R403.2 R404.2 U55.50(AGND) Z18.1(NET1)
AGND_VCCINT_IO_BRAM_PS: R904.1 R911.2 R917.2 U127.13(LGnd) Z62.1(NET1)
GND: C493.2 C495.2 C509.2 C510.2 C511.2 C512.2 C513.2 C514.2 C516.2 C517.2 C518.1 C520.2 C561.2 C564.2 C565.2 C566.2 C568.2 C573.2 C574.2 C1105.2 C1106.2 C1107.2 C1108.2 C1109.2 C1110.2 C1111.2 C1112.2 C1113.2 C1141.2 C1142.2 C1143.2 C1144.2 C1145.2 C1146.2 C1147.2 C1148.2 C1149.2 C1150.2 C1177.1 C1327.2 C1328.2 C1329.2 C1330.2 C1331.2 C1332.2 C1333.2 C1334.2 C1335.2 C1336.2 C1337.2 C1338.2 C1339.2 C1340.2 C1470.2 C1472.2 C1473.2 C1474.2 C1475.2 C1476.2 C1477.2 C1478.2 C1479.2 C1480.2 C1484.2 C1485.2 C1486.2 C1487.2 C1488.2 C1489.2 C1490.2 C1491.2 C1492.2 C1493.2 C1946.2 C1947.2 D4.2(ANODE) R397.2 R406.2 R850.2 R916.2 R1021.2 R1022.2 R1023.2 R1024.2 R1025.2 U55.52(SYNC_CLK) U55.57(GND) U56.4(PGND) U56.5(AGND) U56.13(PGND) U56.14(PGND) U56.15(PGND) U56.28(PGND) U56.31(PGND) U67.7(GND) U112.12_25(PGnd) U127.12_25(PGnd) Z18.2(NET2) Z22.1(NET1) Z27.1(NET1) Z28.2(NET2) Z61.1(NET1) Z62.2(NET2) ; also on sheet 3 4 5 7 8 9 10 11 12 13 14 16 17 18 19 20 21 22 23 24 25 26 27 28 32 33 34 35 36 37 38 39 40 41 42 43 44 45 46 47 52 53 54 55 56 57 58 59 60 61 62 63 64 65 66 67 68 69 70 71 72
VCC1V2: J104.1(P1) R408.I1 Z21.1(NET1) ; also on sheet 4 11 17 25 27 40 41 42 59 65 66 67 68
VCC1V2_BUS: C516.1 C517.1 C1946.1 C1947.1 L33.2 R408.I2 Z20.2(NET2)
VCC1V2_ISEN_IND_P: R409.1 Z19.1(NET1)
VCC1V2_ISEN_N: C519.2 Z20.1(NET1) ; also on sheet 47
VCC1V2_ISEN_P: C519.1 R409.2 ; also on sheet 47
VCC1V2_PWM: R788.1 ; also on sheet 47
VCC1V2_SNS_N: Z22.2(NET2) ; also on sheet 47
VCC1V2_SNS_P: Z21.2(NET2) ; also on sheet 47 56
VCC1V2_SWITCH: L33.1 U56.16(SW) U56.17(SW) U56.18(SW) U56.19(SW) U56.20(SW) U56.21(SW) U56.22(SW) U56.23(SW) Z19.2(NET2)
VCC1V2_VIN_R_N: R408.V1 ; also on sheet 56
VCC1V2_VIN_R_P: R408.V2 ; also on sheet 56
VCC1V8_PGOOD: U55.42(ENA) ; also on sheet 34 52 60
VCC12_SW: C510.1 C511.1 C512.1 C513.1 C514.1 C564.1 C565.1 C566.1 C568.1 C1105.1 C1106.1 C1107.1 C1108.1 C1109.1 C1110.1 C1111.1 C1112.1 C1327.1 C1328.1 C1329.1 C1330.1 C1331.1 C1472.1 C1473.1 C1474.1 C1475.1 C1476.1 C1477.1 C1478.1 C1479.1 C1480.1 U55.1(VIND) U55.2(VIND) U55.3(VIND) U55.12(VINC_1) U55.13(VINC_2) U55.14(VINC_3) U55.32(VINB) U55.39(VINA) U55.49(VSUPPLY) U56.8(VIN) U56.9(VIN) U56.10(VIN) U56.11(VIN) U56.12(VIN) U112.1(PVin) U112.21(Vin) U127.1(PVin) U127.21(Vin) ; also on sheet 28 31 43 44 45 47 52 57 58 62
VCCINT_IO_BRAM_PS: J118.1(P1) R1099.2 Z60.1(NET1) Z79.1(NET1) ; also on sheet 15 16 17 69
VCCINT_IO_BRAM_PS_BUS: C1485.1 C1486.1 C1487.1 C1488.1 C1489.1 C1490.1 C1491.1 C1492.1 C1493.1 L54.2 R1024.1 R1099.1 Z78.1(NET1)
VCCINT_IO_BRAM_PS_PGOOD: U127.11(PGood) ; also on sheet 60
VCCINT_IO_BRAM_PS_SNS_N: R914.2 R915.2 R916.1 Z61.2(NET2)
VCCINT_IO_BRAM_PS_SNS_P: R912.2 R913.2 Z60.2(NET2) ; also on sheet 56
VCCINT_IO_BRAM_PS_SWITCH: C1483.2 L54.1 U127.24(SW)
VCCINT_IO_BRAM_PS_VIN_R_N: Z79.2(NET2) ; also on sheet 56
VCCINT_IO_BRAM_PS_VIN_R_P: Z78.2(NET2) ; also on sheet 56
VCCINT_IO_BRAM_PS_VSNS: R912.1 R917.1 U127.5(Vsns)
INA226_PMBUS_ALERT: U67.3(ALERT) ; also on sheet 22 45 53 54 55 56
INA226_PMBUS_SCL: U67.5(SCL) ; also on sheet 22 45 53 54 55 56
INA226_PMBUS_SDA: U67.2(A0) U67.4(SDA) ; also on sheet 22 45 53 54 55 56
IRPS5401_ALERT_B: U55.17(PMBUS_ALERT_B) U112.17(SAlert#) U127.17(SAlert#) ; also on sheet 22 44 47 52
IRPS5401_SCL: U55.18(PMBUS_CLK) U112.19(SCL) U127.19(SCL) ; also on sheet 22 44 47 52
IRPS5401_SDA: U55.19(PMBUS_DATA) U112.18(SDA) U127.18(SDA) ; also on sheet 22 44 47 52
MGT1V2: J107.1(P1) R400.1(R1) Z16.2(NET2) ; also on sheet 6 15 16 17 18 69
MGT1V2_BUS: C1145.1 C1146.1 C1147.1 C1148.1 C1149.1 C1150.1 L31.2 L32.2 R400.2(R2) R1022.1
MGT1V2_PGOOD: U55.27(PGC) ; also on sheet 47 60
MGT1V2_SNS_P: R1112.2 Z16.1(NET1) ; also on sheet 56
MGT1V2_SWITCHC: C1139.2 L31.1 U55.8(PHASEC_1) U55.9(PHASEC_2) U55.10(PHASEC_3)
MGT1V2_SWITCHD: C1140.2 L32.1 U55.5(PHASED_1) U55.6(PHASED_2) U55.7(PHASED_3)
MGT1V2_VIN_R_N: R400.S1 ; also on sheet 56
MGT1V2_VIN_R_P: R400.S2 ; also on sheet 56
MGTAVCC: J73.1(P1) R455.1(R1) Z26.1(NET1) ; also on sheet 15 18 69
MGTAVCC_BUS: C573.1 C574.1 C1332.1 C1333.1 C1334.1 C1335.1 C1336.1 C1337.1 C1338.1 L35.2 R455.2(R2) R1025.1
MGTAVCC_PGOOD: U55.51(ENC) U55.53(END) U112.11(PGood) ; also on sheet 60
MGTAVCC_SNS_N: R848.2 R849.2 R850.1 Z27.2(NET2)
MGTAVCC_SNS_P: R457.2 R847.2 U67.8(VBUS) Z26.2(NET2)
MGTAVCC_SWITCH: C571.2 L35.1 U112.24(SW)
MGTAVCC_VIN_R_N: R448.2 R455.S1
MGTAVCC_VIN_R_P: R447.2 R455.S2
MGTAVCC_VSNS: R457.1 R459.1 U112.5(Vsns)
MGTRAVCC: C509.1 C1144.1 J108.1(P1) R1023.1 U55.23(VO_LDO) Z17.2(NET2) ; also on sheet 16 18 69
MGTRAVCC_PGOOD: U55.25(PG_LDO) ; also on sheet 60
PMIC3_PHASEA_1_NC: U55.37(PHASEA_1)
PMIC3_PHASEA_2_NC: U55.36(PHASEA_2)
PMIC3_VCC: C492.2 R395.1 U55.29(SLEEP_B) U55.48(VCC)
UTIL_2V5: C1113.1 C1141.1 C1142.1 C1143.1 J106.1(P1) L46.2 R1021.1 U55.22(VIN_LDO) Z71.2(NET2) ; also on sheet 26 40 47 65 66 67 68
UTIL_2V5_PGOOD: U55.30(PGB) ; also on sheet 60
UTIL_2V5_SNS_P: R394.1 R397.1 R1113.2
UTIL_2V5_SWITCH: C1138.2 L46.1 U55.34(PHASEB_2) U55.35(PHASEB_1)
UTIL_3V3: C561.1 C1177.2 R446.1 U55.20(VDDIO) U67.6(VS_P) ; also on sheet 9 10 20 22 23 24 25 26 27 28 29 30 31 33 34 36 37 40 42 43 44 45 47 53 54 55 56 57 59 60 61 64
UTIL_5V0: C520.1 R410.2 U56.29(PVCC) ; also on sheet 20 44 45 53 54 55 58 60 62 64 71 72
UTIL_5V0_PGOOD: U55.28(EN_LDO) U55.44(ENB) U56.1(EN) U112.3(EN/FCCM) U127.3(EN/FCCM) ; also on sheet 47 52 58 60
N17891778: C571.1 R454.2
N18053970: C507.1 R403.1 U55.55(ADDR_PROT)
N18053986: C508.1 R404.1 U55.54(MTP)
N18054150: C1138.1 U55.33(BOOTB)
N18054264: C1139.1 U55.11(BOOTC)
N18054447: C1140.1 U55.4(BOOTD)
N18054578: R405.1 R406.1 U55.24(FB_LDO)
N18054604: C493.1 R395.2 U55.47(VDRV)
N18054628: C495.1 U55.21(1V8)
N18060851: C515.1 U56.7(PHASE)
N18060857: C518.2 R410.1 U56.3(VCC)
N18060887: D4.1(CATHODE) R788.2 U56.2(PWM)
N18060889: J71.1(P1) U56.24(GL) U56.25(GL) U56.26(GL) U56.27(GL) U56.32(GL)
N18062026: C562.1 R448.1 U67.9(VIN_N)
N18062030: C562.2 R447.1 U67.10(VIN_P)
N18062110: R446.2 U67.1(A1)
N20084328: C515.2 R407.1
N20084338: R407.2 U56.6(BOOT)
N22643320: R1113.1 U55.31(FBB)
N22643392: R1112.1 U55.15(FBC)
N24233229: R454.1 U112.2(Boot)
N24233605: R847.1 R848.1 U112.10(RS+)
N24233831: R849.1 U112.9(RS-)
N24235853: R851.2 U112.4(ADDR)
N24236055: C1339.1 U112.22(Vcc)
N24236490: C1340.1 U112.20(P1V8)
N24236567: R852.2 U112.8(RSo)
N24236595: C1341.2 R852.1 R853.2
N24236657: C1341.1 R854.2
N24236679: C1342.1 R853.1 R854.1 R855.1 R856.1 U112.6(FB)
N24236729: C1342.2 C1343.2 U112.7(Comp)
N24236796: C1343.1 R855.2
N24239711: C1483.1 R909.2
N24239751: R909.1 U127.2(Boot)
N24239756: R913.1 R914.1 U127.10(RS+)
N24239762: R915.1 U127.9(RS-)
N24239785: R904.2 U127.4(ADDR)
N24239791: C1470.1 U127.22(Vcc)
N24239794: C1484.1 U127.20(P1V8)
N24239796: R907.2 U127.8(RSo)
N24239797: C1471.2 R906.2 R907.1
N24239798: C1471.1 R905.2
N24239802: C1481.1 R905.1 R906.1 R908.1 R911.1 U127.6(FB)
N24239807: C1481.2 C1482.2 U127.7(Comp)
N24239811: C1482.1 R908.2
N28765303: R394.2 Z71.1(NET1)
N29387156: R1111.2 Z17.1(NET1)
N29387159: R405.2 R1111.1

Not connected (* = marked no-connect by the designer): U55 16(PGD)* 26(PGA)* 38(BOOTA)* 40(RTNA)* 41(FBA)* 43(PWMA)* 45(ISENA-)* 46(ISENA+)* 56(FBD)*; U56 30(PHFLT_B)*; U112 14(SV_CLK)* 15(SV_DIO)* 16(SV_ALERT)* 23(NC1)* 26(NC2)*; U127 14(SV_CLK)* 15(SV_DIO)* 16(SV_ALERT)* 23(NC1)* 26(NC2)*

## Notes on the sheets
sheet 48
- 1.2V @ 6A
sheet 49
- REPLACE IC WITH CORRECT FIRMWARE P/N
- 2.5V @ 500mA
- 1.2V @ 7A
- 0.85V @ 500mA
- MTP: +5
  7-BIT I2C ADDR: 0x15
  7-BIT PMBUS ADDR: 0x45
sheet 50
- REPLACE IC WITH CORRECT FIRMWARE P/N
- 0.85V @ 18A
- OFFSET: +11
  7-BIT I2C ADDR: 0x1B
  7-BIT PMBUS ADDR: 0x4B
sheet 51
- REPLACE IC WITH CORRECT FIRMWARE P/N
- I2C ADDR
  0x46
- 0.9V @ 4A
- OFFSET: +3
  7-BIT I2C ADDR: 0x13
  7-BIT PMBUS ADDR: 0x43
